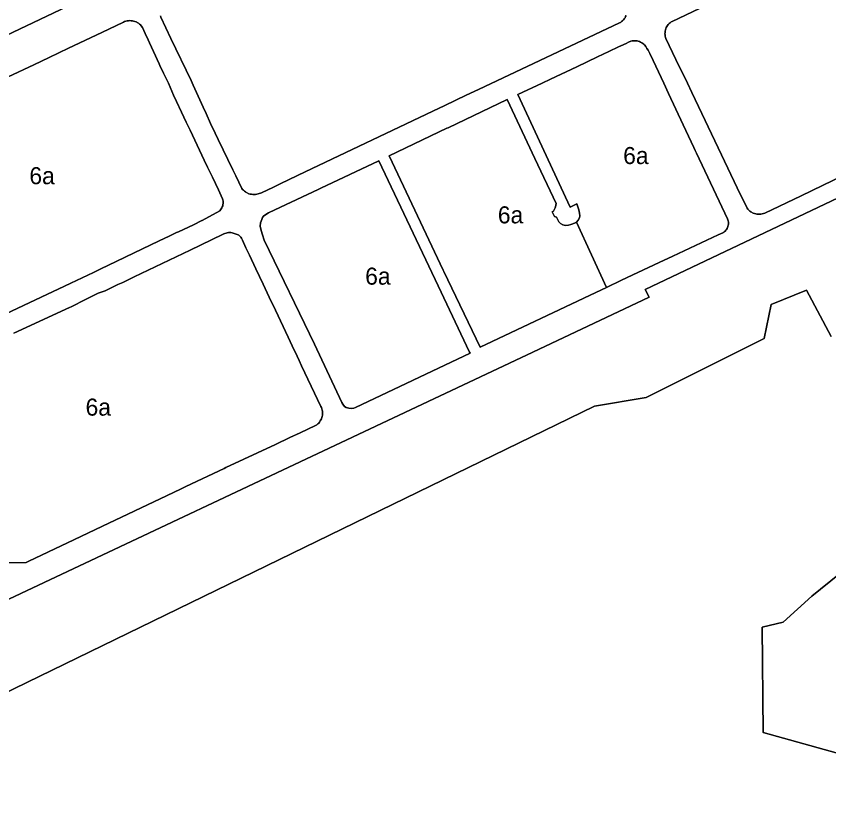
# Model space of a CAD drawing. Extents: x 598968 to 613553, y 4409678 to 4430833.
# Drawn here: x 606081 to 606653, y 4415278 to 4415842 of the extents above; entities that cross this region are included whole.
import ezdxf

# ---------------------------------------------------------------- set-up
doc = ezdxf.new("R2010")
doc.units = 0
for name, color, linetype in [('1', 7, 'Continuous'), ('Nucli Rural', 7, 'Continuous'), ('Polígon industrial de Maó (naus i rafals) - ANNEX III D', 7, 'Continuous'), ('Sòl Rústic Comú', 7, 'Continuous')]:
    doc.layers.add(name, color=color, linetype=linetype)

msp = doc.modelspace()

# ---------------------------------------------------------------- linework, layer by layer
at = {"layer": '1'}
for points in [[(606078.7075, 4416025.8831), (606103.7699, 4415972.6346), (606124.4582, 4415928.8511), (606148.533, 4415878.0414), (606149.8787, 4415875.2337), (606150.3831, 4415873.5761), (606150.7078, 4415871.5086), (606150.7243, 4415869.634), (606150.4163, 4415867.6769), (606149.8743, 4415866.151), (606149.1399, 4415864.7864), (606142.8299, 4415861.7363), (606142.6199, 4415862.1763), (606131.1401, 4415856.4662), (606073.9307, 4415829.0255)], [(606663.3057, 4415730.6265), (606633.156, 4415716.1761), (606607.7963, 4415704.0458), (606605.8263, 4415703.3658), (606604.9163, 4415703.2158), (606603.9863, 4415703.1458), (606603.0663, 4415703.1658), (606602.1463, 4415703.2558), (606601.2363, 4415703.4257), (606600.3463, 4415703.6657), (606599.4763, 4415703.9957), (606597.8464, 4415704.8557), (606597.0864, 4415705.3956), (606596.3864, 4415705.9956), (606595.7364, 4415706.6456), (606595.1464, 4415707.3656), (606588.3064, 4415721.7953), (606577.2964, 4415745.0448), (606556.3964, 4415788.724), (606553.1864, 4415795.3539), (606545.1364, 4415812.1536), (606538.1365, 4415826.7333), (606537.8465, 4415827.5633), (606537.6265, 4415828.4233), (606537.4965, 4415829.3033), (606537.4365, 4415830.1832), (606537.4665, 4415831.0732), (606537.5664, 4415831.9432), (606537.7464, 4415832.8132), (606538.0064, 4415833.6632), (606538.3464, 4415834.4832), (606538.7564, 4415835.2632), (606539.2364, 4415836.0132), (606539.7764, 4415836.7132), (606540.3764, 4415837.3632), (606541.0364, 4415837.9532), (606541.7464, 4415838.4832), (606542.4164, 4415838.8932), (606561.6762, 4415848.0235)], [(606510.1567, 4415843.0327), (606509.7767, 4415842.2027), (606509.3267, 4415841.4127), (606508.8067, 4415840.6627), (606508.2267, 4415839.9527), (606507.5867, 4415839.3126), (606506.8867, 4415838.7226), (606506.1467, 4415838.1926), (606505.3667, 4415837.7426), (606406.2078, 4415790.9715), (606397.6079, 4415786.8814), (606382.5681, 4415779.7312), (606374.2182, 4415775.7711), (606284.3292, 4415732.9701), (606267.2594, 4415724.8099), (606262.0794, 4415722.3399), (606253.5895, 4415718.3098), (606251.1695, 4415717.4697), (606250.2596, 4415717.2597), (606249.3496, 4415717.1197), (606248.4196, 4415717.0697), (606247.4996, 4415717.0897), (606246.5796, 4415717.1996), (606245.6696, 4415717.3796), (606244.7795, 4415717.6396), (606243.0895, 4415718.3796), (606242.5995, 4415718.6796), (606242.2995, 4415718.8596), (606241.5495, 4415719.4095), (606240.8495, 4415720.0195), (606240.2095, 4415720.6895), (606239.6295, 4415721.4095), (606235.4095, 4415730.1793), (606233.3795, 4415734.3792), (606223.1496, 4415755.8788), (606221.0896, 4415760.2087), (606217.8096, 4415767.0986), (606214.5996, 4415774.0185), (606212.4696, 4415778.6284), (606205.6096, 4415794.0081), (606204.0696, 4415797.328), (606189.9096, 4415826.9075), (606182.7796, 4415841.7872), (606182.5496, 4415842.6772)], [(606075.4408, 4415799.7859), (606093.5206, 4415808.3661), (606104.1405, 4415813.4062), (606117.8203, 4415819.9264), (606141.2401, 4415831.0866), (606156.4499, 4415838.3468), (606157.2899, 4415838.6968), (606158.1599, 4415838.9868), (606159.0599, 4415839.1969), (606159.9699, 4415839.3269), (606160.8899, 4415839.3769), (606161.8098, 4415839.3469), (606162.7198, 4415839.2369), (606162.9298, 4415839.1969), (606163.6198, 4415839.0469), (606164.4998, 4415838.7769), (606165.3498, 4415838.437), (606165.7998, 4415838.207), (606166.1698, 4415838.017), (606166.9498, 4415837.537), (606167.6898, 4415836.987), (606168.3798, 4415836.377), (606169.0098, 4415835.7071), (606169.8398, 4415834.6071), (606171.7998, 4415830.2672), (606173.7598, 4415825.9172), (606174.6798, 4415823.8473), (606177.4998, 4415817.5974), (606181.6598, 4415808.8875), (606182.1498, 4415807.8676), (606184.6898, 4415802.5277), (606188.1198, 4415795.3478), (606191.7197, 4415786.8679), (606193.7397, 4415782.608), (606197.3497, 4415774.9882), (606200.6997, 4415767.9083), (606203.3197, 4415762.3584), (606213.3597, 4415741.1288), (606215.6497, 4415736.3189), (606219.0297, 4415729.2191), (606223.2897, 4415720.2792), (606226.2597, 4415714.0493), (606226.4597, 4415713.2394), (606226.5797, 4415712.4194), (606226.6197, 4415711.5994), (606226.5897, 4415710.7694), (606226.4697, 4415709.9494), (606226.2797, 4415709.1494), (606226.0097, 4415708.3594), (606225.6597, 4415707.6094), (606225.2497, 4415706.8894), (606224.7597, 4415706.2194), (606224.1997, 4415705.5794), (606211.9099, 4415698.8593), (606211.7099, 4415698.7693), (606205.6399, 4415695.8292), (606195.2801, 4415690.9191), (606193.8701, 4415690.259), (606188.5301, 4415687.729), (606181.6402, 4415684.4689), (606157.6505, 4415672.9586), (606145.4206, 4415667.0885), (606141.0206, 4415664.9784), (606135.3107, 4415662.2384), (606119.5609, 4415654.6882), (606115.1009, 4415652.5381), (606069.8115, 4415631.2076)], [(605973.5659, 4415384.2565), (606444.3643, 4415606.2638), (606526.3041, 4415644.9028), (606523.4548, 4415650.3535), (606748.099, 4415756.8444)], [(606079.2414, 4415619.4279), (606118.6109, 4415637.4883), (606119.6709, 4415638.0283), (606129.8008, 4415643.1285), (606138.6407, 4415647.5786), (606143.6707, 4415649.4086), (606152.5706, 4415653.6887), (606155.9105, 4415655.2888), (606164.0004, 4415659.1589), (606203.36, 4415678.0193), (606226.2398, 4415688.9696), (606226.9898, 4415689.3796), (606227.7898, 4415689.7196), (606228.6097, 4415689.9796), (606229.4497, 4415690.1696), (606230.3097, 4415690.2797), (606231.1797, 4415690.3097), (606232.0397, 4415690.2597), (606232.8897, 4415690.1297), (606233.7297, 4415689.9197), (606234.2897, 4415689.7297), (606235.8697, 4415689.2098), (606236.4997, 4415688.9998), (606237.1097, 4415688.7198), (606237.6697, 4415688.3698), (606238.1897, 4415687.9598), (606238.6597, 4415687.4798), (606239.0697, 4415686.9598), (606239.4097, 4415686.3799), (606239.6497, 4415685.8599), (606240.1097, 4415684.8799), (606242.5797, 4415679.65), (606245.0998, 4415674.3001), (606249.5897, 4415664.8003), (606254.7097, 4415653.9605), (606258.9997, 4415644.8506), (606261.1097, 4415640.3607), (606261.9397, 4415638.6507), (606263.3897, 4415635.6008), (606272.2697, 4415616.7911), (606275.1497, 4415610.7013), (606278.6197, 4415603.3514), (606280.0497, 4415600.3114), (606281.8097, 4415596.5915), (606295.3297, 4415567.962), (606295.7197, 4415567.1521), (606296.0397, 4415566.3221), (606296.2897, 4415565.4621), (606296.4497, 4415564.5821), (606296.5397, 4415563.6921), (606296.5497, 4415562.8021), (606296.4797, 4415561.9021), (606296.3297, 4415561.0221), (606296.0997, 4415560.1621), (606295.7897, 4415559.3221), (606295.4097, 4415558.5121), (606294.9597, 4415557.7421), (606294.4497, 4415557.0121), (606293.8597, 4415556.3321), (606293.2297, 4415555.7021), (606292.5297, 4415555.1321), (606291.6197, 4415554.5321), (606280.7699, 4415549.422), (606273.5899, 4415546.0419), (606263.5, 4415541.3018), (606228.6003, 4415525.0214), (606227.3603, 4415524.4414), (606200.2406, 4415511.561), (606196.5807, 4415509.821), (606182.2908, 4415503.0408), (606146.0712, 4415485.8604), (606116.9915, 4415472.06), (606089.8619, 4415459.1897), (606087.9919, 4415458.3097), (606075.282, 4415457.8795)]]:
    msp.add_lwpolyline(points, dxfattribs=at)
for points in [[(606496.3175, 4415651.6945), (606488.8276, 4415648.1545), (606407.3277, 4415609.6599), (606381.8467, 4415662.8578), (606381.3187, 4415663.9636), (606343.4029, 4415744.2491), (606383.9782, 4415763.6714), (606384.8581, 4415764.0914), (606426.3262, 4415783.8853), (606445.8976, 4415742.3427), (606460.8076, 4415710.7033), (606460.4076, 4415708.3633), (606460.0987, 4415707.5887), (606459.2095, 4415705.831), (606458.9376, 4415705.3833), (606458.0976, 4415704.8033), (606459.7076, 4415701.5134), (606461.0476, 4415701.1134), (606462.8076, 4415697.8135), (606464.0076, 4415696.7935), (606465.6076, 4415695.8335), (606467.5076, 4415695.3436), (606469.5676, 4415695.4236), (606471.3108, 4415695.9227), (606472.7175, 4415696.5237), (606474.1823, 4415697.0497), (606475.1915, 4415697.7288), (606476.4475, 4415699.0737), (606477.1875, 4415700.5537), (606477.4375, 4415701.9637), (606477.2575, 4415704.0137), (606476.8475, 4415706.3136), (606475.4975, 4415710.4236), (606470.7275, 4415708.1935), (606469.0059, 4415711.7335), (606433.9976, 4415787.532), (606450.9474, 4415795.3522), (606456.8073, 4415798.1422), (606475.3471, 4415806.9425), (606489.987, 4415813.9026), (606497.9869, 4415817.6927), (606504.6968, 4415820.8528), (606506.2943, 4415821.5606), (606510.0838, 4415823.3697), (606511.8067, 4415824.2129), (606513.5167, 4415824.8929), (606514.3667, 4415825.0929), (606515.2267, 4415825.2129), (606516.0967, 4415825.2629), (606516.9667, 4415825.223), (606517.8267, 4415825.103), (606518.6766, 4415824.913), (606519.5066, 4415824.643), (606520.2966, 4415824.293), (606521.0666, 4415823.873), (606521.7866, 4415823.3931), (606522.4566, 4415822.8331), (606522.9966, 4415822.3231), (606523.9066, 4415821.1131), (606524.7566, 4415819.8631), (606525.5366, 4415818.5732), (606526.2466, 4415817.2432), (606526.7366, 4415816.2232), (606529.0466, 4415811.3733), (606536.7066, 4415795.3536), (606540.0066, 4415788.0537), (606550.3466, 4415765.9842), (606557.7666, 4415750.1845), (606558.7366, 4415748.1345), (606559.7066, 4415746.0745), (606581.3965, 4415699.9754), (606581.6765, 4415699.2455), (606581.8965, 4415698.4955), (606582.0265, 4415697.7255), (606582.0765, 4415696.9455), (606582.0565, 4415696.1655), (606581.9565, 4415695.3955), (606581.7665, 4415694.6355), (606581.5065, 4415693.9055), (606581.1766, 4415693.1955), (606580.7666, 4415692.5355), (606580.2966, 4415691.9055), (606579.7666, 4415691.3355), (606579.1866, 4415690.8255), (606578.5466, 4415690.3755), (606578.1566, 4415690.1455), (606574.9366, 4415688.6355), (606542.957, 4415673.6451), (606533.4071, 4415669.165), (606518.3672, 4415662.1148), (606506.9574, 4415656.7247)], [(606318.5495, 4415566.8225), (606316.8395, 4415566.5124), (606315.0595, 4415566.6724), (606313.1995, 4415567.1724), (606312.0395, 4415567.8723), (606310.7295, 4415569.5623), (606310.1495, 4415570.6623), (606290.7658, 4415611.895), (606255.5596, 4415685.0601), (606254.2396, 4415688.6901), (606253.2396, 4415691.69), (606252.7396, 4415694.81), (606252.8796, 4415697.1), (606253.7396, 4415699.44), (606254.2396, 4415700.8099), (606255.0796, 4415701.92), (606256.6095, 4415702.94), (606258.5095, 4415704.2), (606266.9694, 4415708.1501), (606293.4291, 4415720.6404), (606295.2991, 4415721.5204), (606336.0887, 4415740.7808), (606377.8297, 4415652.8053), (606399.9585, 4415606.1634), (606400.3485, 4415605.3434), (606319.6094, 4415567.1525)]]:
    msp.add_lwpolyline(points, close=True, dxfattribs=at)
at = {"layer": 'Nucli Rural'}
msp.add_lwpolyline([(606679.5687, 4415465.9028), (606640.7589, 4415434.4024), (606620.5385, 4415416.3028), (606605.7287, 4415412.6128), (606606.4585, 4415338.4928), (606739.5253, 4415301.4452)], dxfattribs=at)
at = {"layer": 'Polígon industrial de Maó (naus i rafals) - ANNEX III D'}
for points in [[(606073.9307, 4415829.0255), (606131.1401, 4415856.4662), (606142.6199, 4415862.1763), (606142.8299, 4415861.7363), (606149.1399, 4415864.7864), (606149.8743, 4415866.151), (606150.4163, 4415867.6769), (606150.7243, 4415869.634), (606150.7078, 4415871.5086), (606150.3831, 4415873.5761), (606149.8787, 4415875.2337), (606148.533, 4415878.0414), (606124.4582, 4415928.8511), (606103.7699, 4415972.6346), (606078.7075, 4416025.8831)], [(606561.6762, 4415848.0235), (606542.4164, 4415838.8932), (606541.7464, 4415838.4832), (606541.0364, 4415837.9532), (606540.3764, 4415837.3632), (606539.7764, 4415836.7132), (606539.2364, 4415836.0132), (606538.7564, 4415835.2632), (606538.3464, 4415834.4832), (606538.0064, 4415833.6632), (606537.7464, 4415832.8132), (606537.5664, 4415831.9432), (606537.4665, 4415831.0732), (606537.4365, 4415830.1832), (606537.4965, 4415829.3033), (606537.6265, 4415828.4233), (606537.8465, 4415827.5633), (606538.1365, 4415826.7333), (606545.1364, 4415812.1536), (606553.1864, 4415795.3539), (606556.3964, 4415788.724), (606577.2964, 4415745.0448), (606588.3064, 4415721.7953), (606595.1464, 4415707.3656), (606595.7364, 4415706.6456), (606596.3864, 4415705.9956), (606597.0864, 4415705.3956), (606597.8464, 4415704.8557), (606599.4763, 4415703.9957), (606600.3463, 4415703.6657), (606601.2363, 4415703.4257), (606602.1463, 4415703.2558), (606603.0663, 4415703.1658), (606603.9863, 4415703.1458), (606604.9163, 4415703.2158), (606605.8263, 4415703.3658), (606607.7963, 4415704.0458), (606633.156, 4415716.1761), (606663.3057, 4415730.6265)], [(606182.5496, 4415842.6772), (606182.7796, 4415841.7872), (606189.9096, 4415826.9075), (606204.0696, 4415797.328), (606205.6096, 4415794.0081), (606212.4696, 4415778.6284), (606214.5996, 4415774.0185), (606217.8096, 4415767.0986), (606221.0896, 4415760.2087), (606223.1496, 4415755.8788), (606233.3795, 4415734.3792), (606235.4095, 4415730.1793), (606239.6295, 4415721.4095), (606240.2095, 4415720.6895), (606240.8495, 4415720.0195), (606241.5495, 4415719.4095), (606242.2995, 4415718.8596), (606242.5995, 4415718.6796), (606243.0895, 4415718.3796), (606244.7795, 4415717.6396), (606245.6696, 4415717.3796), (606246.5796, 4415717.1996), (606247.4996, 4415717.0897), (606248.4196, 4415717.0697), (606249.3496, 4415717.1197), (606250.2596, 4415717.2597), (606251.1695, 4415717.4697), (606253.5895, 4415718.3098), (606262.0794, 4415722.3399), (606267.2594, 4415724.8099), (606284.3292, 4415732.9701), (606374.2182, 4415775.7711), (606382.5681, 4415779.7312), (606397.6079, 4415786.8814), (606406.2078, 4415790.9715), (606505.3667, 4415837.7426), (606506.1467, 4415838.1926), (606506.8867, 4415838.7226), (606507.5867, 4415839.3126), (606508.2267, 4415839.9527), (606508.8067, 4415840.6627), (606509.3267, 4415841.4127), (606509.7767, 4415842.2027), (606510.1567, 4415843.0327)], [(606069.8115, 4415631.2076), (606115.1009, 4415652.5381), (606119.5609, 4415654.6882), (606135.3107, 4415662.2384), (606141.0206, 4415664.9784), (606145.4206, 4415667.0885), (606157.6505, 4415672.9586), (606181.6402, 4415684.4689), (606188.5301, 4415687.729), (606193.8701, 4415690.259), (606195.2801, 4415690.9191), (606205.6399, 4415695.8292), (606211.7099, 4415698.7693), (606211.9099, 4415698.8593), (606224.1997, 4415705.5794), (606224.7597, 4415706.2194), (606225.2497, 4415706.8894), (606225.6597, 4415707.6094), (606226.0097, 4415708.3594), (606226.2797, 4415709.1494), (606226.4697, 4415709.9494), (606226.5897, 4415710.7694), (606226.6197, 4415711.5994), (606226.5797, 4415712.4194), (606226.4597, 4415713.2394), (606226.2597, 4415714.0493), (606223.2897, 4415720.2792), (606219.0297, 4415729.2191), (606215.6497, 4415736.3189), (606213.3597, 4415741.1288), (606203.3197, 4415762.3584), (606200.6997, 4415767.9083), (606197.3497, 4415774.9882), (606193.7397, 4415782.608), (606191.7197, 4415786.8679), (606188.1198, 4415795.3478), (606184.6898, 4415802.5277), (606182.1498, 4415807.8676), (606181.6598, 4415808.8875), (606177.4998, 4415817.5974), (606174.6798, 4415823.8473), (606173.7598, 4415825.9172), (606171.7998, 4415830.2672), (606169.8398, 4415834.6071), (606169.0098, 4415835.7071), (606168.3798, 4415836.377), (606167.6898, 4415836.987), (606166.9498, 4415837.537), (606166.1698, 4415838.017), (606165.7998, 4415838.207), (606165.3498, 4415838.437), (606164.4998, 4415838.7769), (606163.6198, 4415839.0469), (606162.9298, 4415839.1969), (606162.7198, 4415839.2369), (606161.8098, 4415839.3469), (606160.8899, 4415839.3769), (606159.9699, 4415839.3269), (606159.0599, 4415839.1969), (606158.1599, 4415838.9868), (606157.2899, 4415838.6968), (606156.4499, 4415838.3468), (606141.2401, 4415831.0866), (606117.8203, 4415819.9264), (606104.1405, 4415813.4062), (606093.5206, 4415808.3661), (606075.4408, 4415799.7859)], [(606075.282, 4415457.8795), (606087.9919, 4415458.3097), (606089.8619, 4415459.1897), (606116.9915, 4415472.06), (606146.0712, 4415485.8604), (606182.2908, 4415503.0408), (606196.5807, 4415509.821), (606200.2406, 4415511.561), (606227.3603, 4415524.4414), (606228.6003, 4415525.0214), (606263.5, 4415541.3018), (606273.5899, 4415546.0419), (606280.7699, 4415549.422), (606291.6197, 4415554.5321), (606292.5297, 4415555.1321), (606293.2297, 4415555.7021), (606293.8597, 4415556.3321), (606294.4497, 4415557.0121), (606294.9597, 4415557.7421), (606295.4097, 4415558.5121), (606295.7897, 4415559.3221), (606296.0997, 4415560.1621), (606296.3297, 4415561.0221), (606296.4797, 4415561.9021), (606296.5497, 4415562.8021), (606296.5397, 4415563.6921), (606296.4497, 4415564.5821), (606296.2897, 4415565.4621), (606296.0397, 4415566.3221), (606295.7197, 4415567.1521), (606295.3297, 4415567.962), (606281.8097, 4415596.5915), (606280.0497, 4415600.3114), (606278.6197, 4415603.3514), (606275.1497, 4415610.7013), (606272.2697, 4415616.7911), (606263.3897, 4415635.6008), (606261.9397, 4415638.6507), (606261.1097, 4415640.3607), (606258.9997, 4415644.8506), (606254.7097, 4415653.9605), (606249.5897, 4415664.8003), (606245.0998, 4415674.3001), (606242.5797, 4415679.65), (606240.1097, 4415684.8799), (606239.6497, 4415685.8599), (606239.4097, 4415686.3799), (606239.0697, 4415686.9598), (606238.6597, 4415687.4798), (606238.1897, 4415687.9598), (606237.6697, 4415688.3698), (606237.1097, 4415688.7198), (606236.4997, 4415688.9998), (606235.8697, 4415689.2098), (606234.2897, 4415689.7297), (606233.7297, 4415689.9197), (606232.8897, 4415690.1297), (606232.0397, 4415690.2597), (606231.1797, 4415690.3097), (606230.3097, 4415690.2797), (606229.4497, 4415690.1696), (606228.6097, 4415689.9796), (606227.7898, 4415689.7196), (606226.9898, 4415689.3796), (606226.2398, 4415688.9696), (606203.36, 4415678.0193), (606164.0004, 4415659.1589), (606155.9105, 4415655.2888), (606152.5706, 4415653.6887), (606143.6707, 4415649.4086), (606138.6407, 4415647.5786), (606129.8008, 4415643.1285), (606119.6709, 4415638.0283), (606118.6109, 4415637.4883), (606079.2414, 4415619.4279)]]:
    msp.add_lwpolyline(points, dxfattribs=at)
for points in [[(606496.3175, 4415651.6945), (606506.9574, 4415656.7247), (606518.3672, 4415662.1148), (606533.4071, 4415669.165), (606542.957, 4415673.6451), (606574.9366, 4415688.6355), (606578.1566, 4415690.1455), (606578.5466, 4415690.3755), (606579.1866, 4415690.8255), (606579.7666, 4415691.3355), (606580.2966, 4415691.9055), (606580.7666, 4415692.5355), (606581.1766, 4415693.1955), (606581.5065, 4415693.9055), (606581.7665, 4415694.6355), (606581.9565, 4415695.3955), (606582.0565, 4415696.1655), (606582.0765, 4415696.9455), (606582.0265, 4415697.7255), (606581.8965, 4415698.4955), (606581.6765, 4415699.2455), (606581.3965, 4415699.9754), (606559.7066, 4415746.0745), (606558.7366, 4415748.1345), (606557.7666, 4415750.1845), (606550.3466, 4415765.9842), (606540.0066, 4415788.0537), (606536.7066, 4415795.3536), (606529.0466, 4415811.3733), (606526.7366, 4415816.2232), (606526.2466, 4415817.2432), (606525.5366, 4415818.5732), (606524.7566, 4415819.8631), (606523.9066, 4415821.1131), (606522.9966, 4415822.3231), (606522.4566, 4415822.8331), (606521.7866, 4415823.3931), (606521.0666, 4415823.873), (606520.2966, 4415824.293), (606519.5066, 4415824.643), (606518.6766, 4415824.913), (606517.8267, 4415825.103), (606516.9667, 4415825.223), (606516.0967, 4415825.2629), (606515.2267, 4415825.2129), (606514.3667, 4415825.0929), (606513.5167, 4415824.8929), (606511.8067, 4415824.2129), (606510.0838, 4415823.3697), (606506.2943, 4415821.5606), (606504.6968, 4415820.8528), (606497.9869, 4415817.6927), (606489.987, 4415813.9026), (606475.3471, 4415806.9425), (606456.8073, 4415798.1422), (606450.9474, 4415795.3522), (606433.9976, 4415787.532), (606469.0059, 4415711.7335), (606470.7275, 4415708.1935), (606475.4975, 4415710.4236), (606476.8475, 4415706.3136), (606477.2575, 4415704.0137), (606477.4375, 4415701.9637), (606477.1875, 4415700.5537), (606476.4475, 4415699.0737), (606475.1915, 4415697.7288)], [(606475.1915, 4415697.7288), (606474.1823, 4415697.0497), (606472.7175, 4415696.5237), (606471.3108, 4415695.9227), (606469.5676, 4415695.4236), (606467.5076, 4415695.3436), (606465.6076, 4415695.8335), (606464.0076, 4415696.7935), (606462.8076, 4415697.8135), (606461.0476, 4415701.1134), (606459.7076, 4415701.5134), (606458.0976, 4415704.8033), (606458.9376, 4415705.3833), (606459.2095, 4415705.831), (606460.0987, 4415707.5887), (606460.4076, 4415708.3633), (606460.8076, 4415710.7033), (606445.8976, 4415742.3427), (606426.3262, 4415783.8853), (606384.8581, 4415764.0914), (606383.9782, 4415763.6714), (606343.4029, 4415744.2491), (606381.3187, 4415663.9636), (606381.8467, 4415662.8578), (606407.3277, 4415609.6599), (606488.8276, 4415648.1545), (606496.3175, 4415651.6945)], [(606318.5495, 4415566.8225), (606319.6094, 4415567.1525), (606400.3485, 4415605.3434), (606399.9585, 4415606.1634), (606377.8297, 4415652.8053), (606336.0887, 4415740.7808), (606295.2991, 4415721.5204), (606293.4291, 4415720.6404), (606266.9694, 4415708.1501), (606258.5095, 4415704.2), (606256.6095, 4415702.94), (606255.0796, 4415701.92), (606254.2396, 4415700.8099), (606253.7396, 4415699.44), (606252.8796, 4415697.1), (606252.7396, 4415694.81), (606253.2396, 4415691.69), (606254.2396, 4415688.6901), (606255.5596, 4415685.0601), (606290.7658, 4415611.895), (606310.1495, 4415570.6623), (606310.7295, 4415569.5623), (606312.0395, 4415567.8723), (606313.1995, 4415567.1724), (606315.0595, 4415566.6724), (606316.8395, 4415566.5124)]]:
    msp.add_lwpolyline(points, close=True, dxfattribs=at)
at = {"layer": 'Sòl Rústic Comú'}
for points in [[(606748.099, 4415756.8444), (606523.4548, 4415650.3535), (606526.3041, 4415644.9028), (606444.3643, 4415606.2638), (605973.5659, 4415384.2565), (605922.3502, 4415361.5323), (605879.4637, 4415341.5373), (605850.355, 4415326.8812), (605825.1238, 4415315.8187), (605810.0857, 4415308.7421), (605797.8641, 4415302.9909), (605797.5694, 4415302.8522), (605793.6554, 4415309.4444), (605793.3719, 4415309.9219), (605752.1398, 4415290.8862), (605722.6392, 4415277.2668)], [(605729.9823, 4415246.6932), (605910.7971, 4415332.1936), (605932.1721, 4415307.1936), (605963.9225, 4415313.1936), (606487.8665, 4415568.1946), (606524.1169, 4415574.1946), (606607.1803, 4415615.6948), (606612.0555, 4415639.6948), (606636.9933, 4415649.6948), (606654.3683, 4415617.1948)], [(606654.3683, 4415617.1948), (606636.9933, 4415649.6948), (606612.0555, 4415639.6948), (606607.1803, 4415615.6948), (606524.1169, 4415574.1946), (606487.8665, 4415568.1946), (605963.9225, 4415313.1936), (605932.1721, 4415307.1936), (605910.7971, 4415332.1936), (605729.9823, 4415246.6932)], [(606739.5253, 4415301.4452), (606606.4585, 4415338.4928), (606605.7287, 4415412.6128), (606620.5385, 4415416.3028), (606640.7589, 4415434.4024), (606679.5687, 4415465.9028)]]:
    msp.add_lwpolyline(points, dxfattribs=at)

# ---------------------------------------------------------------- texts
at = {"layer": 'Polígon industrial de Maó (naus i rafals) - ANNEX III D'}
for p in [(606508.0371, 4415738.4787), (606090.2799, 4415724.3069), (606419.8602, 4415696.7726), (606326.5441, 4415653.6466), (606129.8212, 4415561.5043)]:
    msp.add_text('6a', height=12, dxfattribs=at).set_placement(p)

doc.saveas('drawing.dxf')
